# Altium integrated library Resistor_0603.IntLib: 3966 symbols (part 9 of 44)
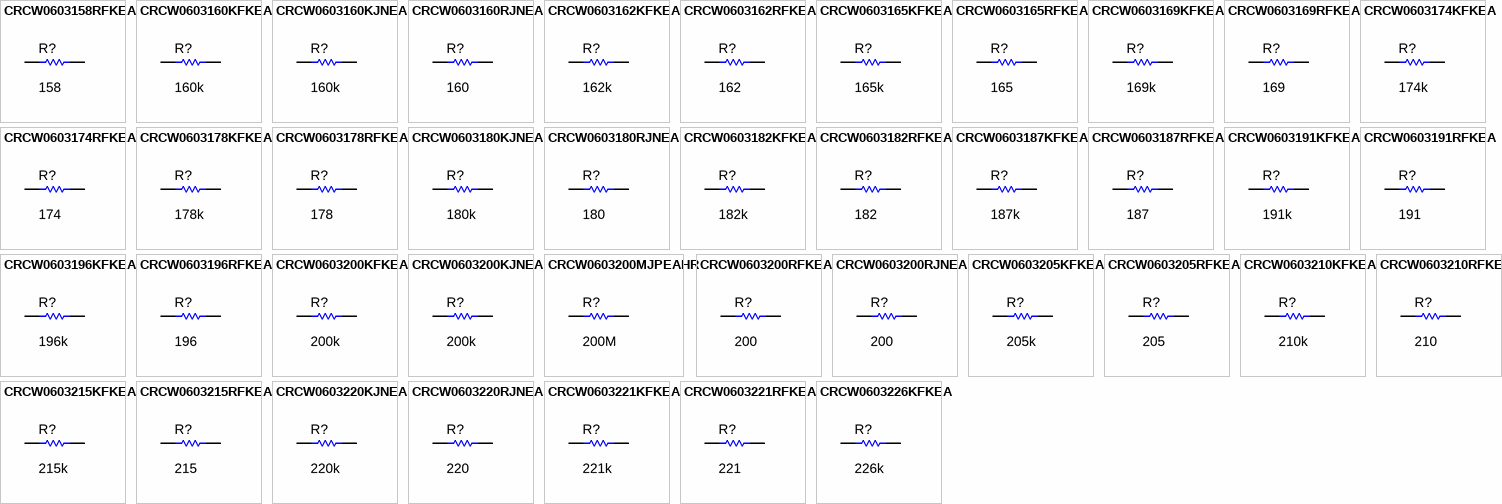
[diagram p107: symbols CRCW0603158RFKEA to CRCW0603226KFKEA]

## CRCW0603221RFKEA
designator R?  ValueDisplayed: 221  (hidden comment: CRCW0603221RFKEA)
RES, 221, 1%, 0.1 W, 0603; Manufacturer: Vishay-Dale; CompType: Resistor; Value: 221; Value_Code: 221R; Tolerance_%: 1; Power_W: 0.1; Value2: 0.1W; VDC_V: 75; TempCo: 100 ppm/C; SizeArea_mm2: 1.28; SizeX_mm: 1.6; SizeY_mm: 0.8; EIA_Code: E96; U/M: EA; AEC Category: Q200; Green_Lifecycle: Active; Green_REACh: Passed
signal-integrity model Resistor
simulation model Resistor
footprint 0603
footprint 0603M
footprint 0603L
footprint 0603_HV
footprint 0603S
pins: 1, 2

## CRCW0603226KFKEA
designator R?  ValueDisplayed: 226k  (hidden comment: CRCW0603226KFKEA)
RES, 226 k, 1%, 0.1 W, 0603; Manufacturer: Vishay-Dale; CompType: Resistor; Value: 226k; Res_ohm: 226000; Tolerance_%: 1; Power_W: 0.1; Value2: 0.1W; VDC_V: 75; TempCo: 100 ppm/C; SizeArea_mm2: 1.28; SizeX_mm: 1.6; SizeY_mm: 0.8; EIA_Code: E96; U/M: EA; AEC Category: Q200; Green_Lifecycle: Active; Green_REACh: Passed
signal-integrity model Resistor
simulation model Resistor
footprint 0603
footprint 0603M
footprint 0603L
footprint 0603_HV
footprint 0603S
pins: 1, 2

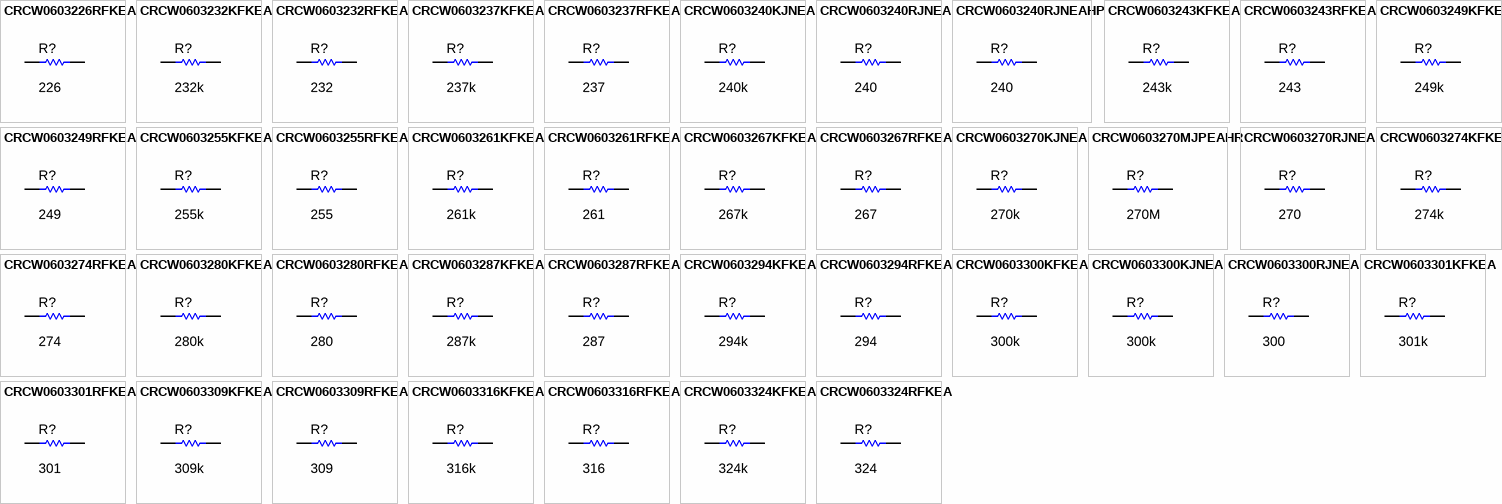
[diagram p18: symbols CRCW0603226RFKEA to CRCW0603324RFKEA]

## CRCW0603226RFKEA
designator R?  ValueDisplayed: 226  (hidden comment: CRCW0603226RFKEA)
RES, 226, 1%, 0.1 W, 0603; Manufacturer: Vishay-Dale; CompType: Resistor; Value: 226; Value_Code: 226R; Tolerance_%: 1; Power_W: 0.1; Value2: 0.1W; VDC_V: 75; TempCo: 100 ppm/C; SizeArea_mm2: 1.28; SizeX_mm: 1.6; SizeY_mm: 0.8; EIA_Code: E96; U/M: EA; AEC Category: Q200
signal-integrity model Resistor
simulation model Resistor
footprint 0603
footprint 0603M
footprint 0603L
footprint 0603_HV
footprint 0603S
pins: 1, 2

## CRCW0603232KFKEA
designator R?  ValueDisplayed: 232k  (hidden comment: CRCW0603232KFKEA)
RES, 232 k, 1%, 0.1 W, 0603; Manufacturer: Vishay-Dale; CompType: Resistor; Value: 232k; Res_ohm: 232000; Tolerance_%: 1; Power_W: 0.1; Value2: 0.1W; VDC_V: 75; TempCo: 100 ppm/C; SizeArea_mm2: 1.28; SizeX_mm: 1.6; SizeY_mm: 0.8; EIA_Code: E96; U/M: EA; AEC Category: Q200; Green_Lifecycle: Active; Green_REACh: Passed
signal-integrity model Resistor
simulation model Resistor
footprint 0603
footprint 0603M
footprint 0603L
footprint 0603_HV
footprint 0603S
pins: 1, 2

## CRCW0603232RFKEA
designator R?  ValueDisplayed: 232  (hidden comment: CRCW0603232RFKEA)
RES, 232, 1%, 0.1 W, 0603; Manufacturer: Vishay-Dale; CompType: Resistor; Value: 232; Value_Code: 232R; Tolerance_%: 1; Power_W: 0.1; Value2: 0.1W; VDC_V: 75; TempCo: 100 ppm/C; SizeArea_mm2: 1.28; SizeX_mm: 1.6; SizeY_mm: 0.8; EIA_Code: E96; U/M: EA; AEC Category: Q200
signal-integrity model Resistor
simulation model Resistor
footprint 0603
footprint 0603M
footprint 0603L
footprint 0603_HV
footprint 0603S
pins: 1, 2

## CRCW0603237KFKEA
designator R?  ValueDisplayed: 237k  (hidden comment: CRCW0603237KFKEA)
RES, 237 k, 1%, 0.1 W, 0603; Manufacturer: Vishay-Dale; CompType: Resistor; Value: 237k; Res_ohm: 237000; Tolerance_%: 1; Power_W: 0.1; Value2: 0.1W; VDC_V: 75; TempCo: 100 ppm/C; SizeArea_mm2: 1.28; SizeX_mm: 1.6; SizeY_mm: 0.8; EIA_Code: E96; U/M: EA; AEC Category: Q200; Green_Lifecycle: Active; Green_REACh: Passed
signal-integrity model Resistor
simulation model Resistor
footprint 0603
footprint 0603M
footprint 0603L
footprint 0603_HV
footprint 0603S
pins: 1, 2

## CRCW0603237RFKEA
designator R?  ValueDisplayed: 237  (hidden comment: CRCW0603237RFKEA)
RES, 237, 1%, 0.1 W, 0603; Manufacturer: Vishay-Dale; CompType: Resistor; Value: 237; Value_Code: 237R; Tolerance_%: 1; Power_W: 0.1; Value2: 0.1W; VDC_V: 75; TempCo: 100 ppm/C; SizeArea_mm2: 1.28; SizeX_mm: 1.6; SizeY_mm: 0.8; EIA_Code: E96; U/M: EA; AEC Category: Q200; Green_Lifecycle: Active; Green_REACh: Passed
signal-integrity model Resistor
simulation model Resistor
footprint 0603
footprint 0603M
footprint 0603L
footprint 0603_HV
footprint 0603S
pins: 1, 2

## CRCW0603240KJNEA
designator R?  ValueDisplayed: 240k  (hidden comment: CRCW0603240KJNEA)
RES, 240 k, 5%, 0.1 W, 0603; Manufacturer: Vishay-Dale; CompType: Resistor; Value: 240k; Res_ohm: 240000; Tolerance_%: 5; Power_W: 0.1; Value2: 0.1W; VDC_V: 75; TempCo: 200 ppm/C; SizeArea_mm2: 1.28; SizeX_mm: 1.6; SizeY_mm: 0.8; SizeZ_mm: 1; EIA_Code: E24; U/M: EA; AEC Category: Q200; Green_Lifecycle: Active; Green_REACh: Passed
signal-integrity model Resistor
simulation model Resistor
footprint 0603
footprint 0603M
footprint 0603L
footprint 0603_HV
footprint 0603S
pins: 1, 2

## CRCW0603240RJNEA
designator R?  ValueDisplayed: 240  (hidden comment: CRCW0603240RJNEA)
RES, 240, 5%, 0.1 W, 0603; Manufacturer: Vishay-Dale; CompType: Resistor; Value: 240; Value_Code: 240R; Tolerance_%: 5; Power_W: 0.1; Value2: 0.1W; VDC_V: 75; TempCo: 200 ppm/C; SizeArea_mm2: 1.28; SizeX_mm: 1.6; SizeY_mm: 0.8; SizeZ_mm: 1; EIA_Code: E24; U/M: EA; AEC Category: Q200; Green_Lifecycle: Active; Green_REACh: Passed
signal-integrity model Resistor
simulation model Resistor
footprint 0603
footprint 0603M
footprint 0603L
footprint 0603_HV
footprint 0603S
pins: 1, 2

## CRCW0603240RJNEAHP
designator R?  ValueDisplayed: 240  (hidden comment: CRCW0603240RJNEAHP)
RES, 240, 5%, 0.25 W, 0603; Manufacturer: Vishay-Dale; CompType: Resistor; Value: 240; Value_Code: 240R; Tolerance_%: 5; Power_W: 0.25; Value2: 0.25W; VDC_V: 75; TempCo: 200 ppm/C; SizeArea_mm2: 1.28; SizeX_mm: 1.6; SizeY_mm: 0.8; SizeZ_mm: 1; EIA_Code: E24; U/M: EA; AEC Category: Q200
signal-integrity model Resistor
simulation model Resistor
footprint 0603
footprint 0603M
footprint 0603L
footprint 0603_HV
footprint 0603S
pins: 1, 2

## CRCW0603243KFKEA
designator R?  ValueDisplayed: 243k  (hidden comment: CRCW0603243KFKEA)
RES, 243 k, 1%, 0.1 W, 0603; Manufacturer: Vishay-Dale; CompType: Resistor; Value: 243k; Res_ohm: 243000; Tolerance_%: 1; Power_W: 0.1; Value2: 0.1W; VDC_V: 75; TempCo: 100 ppm/C; SizeArea_mm2: 1.28; SizeX_mm: 1.6; SizeY_mm: 0.8; EIA_Code: E96; U/M: EA; AEC Category: Q200; Green_Lifecycle: Active; Green_REACh: Passed
signal-integrity model Resistor
simulation model Resistor
footprint 0603
footprint 0603M
footprint 0603L
footprint 0603_HV
footprint 0603S
pins: 1, 2

## CRCW0603243RFKEA
designator R?  ValueDisplayed: 243  (hidden comment: CRCW0603243RFKEA)
RES, 243, 1%, 0.1 W, 0603; Manufacturer: Vishay-Dale; CompType: Resistor; Value: 243; Value_Code: 243R; Tolerance_%: 1; Power_W: 0.1; Value2: 0.1W; VDC_V: 75; TempCo: 100 ppm/C; SizeArea_mm2: 1.28; SizeX_mm: 1.6; SizeY_mm: 0.8; EIA_Code: E96; U/M: EA; AEC Category: Q200
signal-integrity model Resistor
simulation model Resistor
footprint 0603
footprint 0603M
footprint 0603L
footprint 0603_HV
footprint 0603S
pins: 1, 2

## CRCW0603249KFKEA
designator R?  ValueDisplayed: 249k  (hidden comment: CRCW0603249KFKEA)
RES, 249 k, 1%, 0.1 W, 0603; Manufacturer: Vishay-Dale; CompType: Resistor; Value: 249k; Res_ohm: 249000; Tolerance_%: 1; Power_W: 0.1; Value2: 0.1W; VDC_V: 75; TempCo: 100 ppm/C; SizeArea_mm2: 1.28; SizeX_mm: 1.6; SizeY_mm: 0.8; EIA_Code: E96; U/M: EA; AEC Category: Q200; Green_Lifecycle: Active; Green_REACh: Passed
signal-integrity model Resistor
simulation model Resistor
footprint 0603
footprint 0603M
footprint 0603L
footprint 0603_HV
footprint 0603S
pins: 1, 2

## CRCW0603249RFKEA
designator R?  ValueDisplayed: 249  (hidden comment: CRCW0603249RFKEA)
RES, 249, 1%, 0.1 W, 0603; Manufacturer: Vishay-Dale; CompType: Resistor; Value: 249; Value_Code: 249R; Tolerance_%: 1; Power_W: 0.1; Value2: 0.1W; VDC_V: 75; TempCo: 100 ppm/C; SizeArea_mm2: 1.28; SizeX_mm: 1.6; SizeY_mm: 0.8; EIA_Code: E96; U/M: EA; AEC Category: Q200; Green_Lifecycle: Active; Green_REACh: Passed
signal-integrity model Resistor
simulation model Resistor
footprint 0603
footprint 0603M
footprint 0603L
footprint 0603_HV
footprint 0603S
pins: 1, 2

## CRCW0603255KFKEA
designator R?  ValueDisplayed: 255k  (hidden comment: CRCW0603255KFKEA)
RES, 255 k, 1%, 0.1 W, 0603; Manufacturer: Vishay-Dale; CompType: Resistor; Value: 255k; Res_ohm: 255000; Tolerance_%: 1; Power_W: 0.1; Value2: 0.1W; VDC_V: 75; TempCo: 100 ppm/C; SizeArea_mm2: 1.28; SizeX_mm: 1.6; SizeY_mm: 0.8; EIA_Code: E96; U/M: EA; AEC Category: Q200; Green_Lifecycle: Active; Green_REACh: Passed
signal-integrity model Resistor
simulation model Resistor
footprint 0603
footprint 0603M
footprint 0603L
footprint 0603_HV
footprint 0603S
pins: 1, 2

## CRCW0603255RFKEA
designator R?  ValueDisplayed: 255  (hidden comment: CRCW0603255RFKEA)
RES, 255, 1%, 0.1 W, 0603; Manufacturer: Vishay-Dale; CompType: Resistor; Value: 255; Value_Code: 255R; Tolerance_%: 1; Power_W: 0.1; Value2: 0.1W; VDC_V: 75; TempCo: 100 ppm/C; SizeArea_mm2: 1.28; SizeX_mm: 1.6; SizeY_mm: 0.8; EIA_Code: E96; U/M: EA; AEC Category: Q200
signal-integrity model Resistor
simulation model Resistor
footprint 0603
footprint 0603M
footprint 0603L
footprint 0603_HV
footprint 0603S
pins: 1, 2

## CRCW0603261KFKEA
designator R?  ValueDisplayed: 261k  (hidden comment: CRCW0603261KFKEA)
RES, 261 k, 1%, 0.1 W, 0603; Manufacturer: Vishay-Dale; CompType: Resistor; Value: 261k; Res_ohm: 261000; Tolerance_%: 1; Power_W: 0.1; Value2: 0.1W; VDC_V: 75; TempCo: 100 ppm/C; SizeArea_mm2: 1.28; SizeX_mm: 1.6; SizeY_mm: 0.8; EIA_Code: E96; U/M: EA; AEC Category: Q200; Green_Lifecycle: Active; Green_REACh: Passed
signal-integrity model Resistor
simulation model Resistor
footprint 0603
footprint 0603M
footprint 0603L
footprint 0603_HV
footprint 0603S
pins: 1, 2

## CRCW0603261RFKEA
designator R?  ValueDisplayed: 261  (hidden comment: CRCW0603261RFKEA)
RES, 261, 1%, 0.1 W, 0603; Manufacturer: Vishay-Dale; CompType: Resistor; Value: 261; Value_Code: 261R; Tolerance_%: 1; Power_W: 0.1; Value2: 0.1W; VDC_V: 75; TempCo: 100 ppm/C; SizeArea_mm2: 1.28; SizeX_mm: 1.6; SizeY_mm: 0.8; EIA_Code: E96; U/M: EA; AEC Category: Q200; Green_Lifecycle: Active; Green_REACh: Passed
signal-integrity model Resistor
simulation model Resistor
footprint 0603
footprint 0603M
footprint 0603L
footprint 0603_HV
footprint 0603S
pins: 1, 2

## CRCW0603267KFKEA
designator R?  ValueDisplayed: 267k  (hidden comment: CRCW0603267KFKEA)
RES, 267 k, 1%, 0.1 W, 0603; Manufacturer: Vishay-Dale; CompType: Resistor; Value: 267k; Res_ohm: 267000; Tolerance_%: 1; Power_W: 0.1; Value2: 0.1W; VDC_V: 75; TempCo: 100 ppm/C; SizeArea_mm2: 1.28; SizeX_mm: 1.6; SizeY_mm: 0.8; EIA_Code: E96; U/M: EA; AEC Category: Q200; Green_Lifecycle: Active; Green_REACh: Passed
signal-integrity model Resistor
simulation model Resistor
footprint 0603
footprint 0603M
footprint 0603L
footprint 0603_HV
footprint 0603S
pins: 1, 2

## CRCW0603267RFKEA
designator R?  ValueDisplayed: 267  (hidden comment: CRCW0603267RFKEA)
RES, 267, 1%, 0.1 W, 0603; Manufacturer: Vishay-Dale; CompType: Resistor; Value: 267; Value_Code: 267R; Tolerance_%: 1; Power_W: 0.1; Value2: 0.1W; VDC_V: 75; TempCo: 100 ppm/C; SizeArea_mm2: 1.28; SizeX_mm: 1.6; SizeY_mm: 0.8; EIA_Code: E96; U/M: EA; AEC Category: Q200; Green_Lifecycle: Active; Green_REACh: Passed
signal-integrity model Resistor
simulation model Resistor
footprint 0603
footprint 0603M
footprint 0603L
footprint 0603_HV
footprint 0603S
pins: 1, 2

## CRCW0603270KJNEA
designator R?  ValueDisplayed: 270k  (hidden comment: CRCW0603270KJNEA)
RES, 270 k, 5%, 0.1 W, 0603; Manufacturer: Vishay-Dale; CompType: Resistor; Value: 270k; Res_ohm: 270000; Tolerance_%: 5; Power_W: 0.1; Value2: 0.1W; VDC_V: 75; TempCo: 200 ppm/C; SizeArea_mm2: 1.28; SizeX_mm: 1.6; SizeY_mm: 0.8; SizeZ_mm: 1; EIA_Code: E24; U/M: EA; AEC Category: Q200
signal-integrity model Resistor
simulation model Resistor
footprint 0603
footprint 0603M
footprint 0603L
footprint 0603_HV
footprint 0603S
pins: 1, 2

## CRCW0603270MJPEAHR
designator R?  ValueDisplayed: 270M  (hidden comment: CRCW0603270MJPEAHR)
RES, 270 M, 5%, 0.1 W, 0603; Manufacturer: Vishay-Dale; CompType: Resistor; Value: 270Meg; Res_ohm: 270000000; Tolerance_%: 5; Power_W: 0.1; Value2: 0.1W; VDC_V: 75; TempCo: 500 ppm/C; SizeArea_mm2: 1.3175; SizeX_mm: 1.55; SizeY_mm: 0.85; SizeZ_mm: 0.5; U/M: EA; AEC Category: Q200; AEC Qualified: N
signal-integrity model Resistor
simulation model Resistor
footprint D11_0603
pins: 1, 2

## CRCW0603270RJNEA
designator R?  ValueDisplayed: 270  (hidden comment: CRCW0603270RJNEA)
RES, 270, 5%, 0.1 W, 0603; Manufacturer: Vishay-Dale; CompType: Resistor; Value: 270; Value_Code: 270R; Tolerance_%: 5; Power_W: 0.1; Value2: 0.1W; VDC_V: 75; TempCo: 200 ppm/C; SizeArea_mm2: 1.28; SizeX_mm: 1.6; SizeY_mm: 0.8; SizeZ_mm: 1; EIA_Code: E24; U/M: EA; AEC Category: Q200; Green_Lifecycle: Active; Green_REACh: Passed
signal-integrity model Resistor
simulation model Resistor
footprint 0603
footprint 0603M
footprint 0603L
footprint 0603_HV
footprint 0603S
pins: 1, 2

## CRCW0603274KFKEA
designator R?  ValueDisplayed: 274k  (hidden comment: CRCW0603274KFKEA)
RES, 274 k, 1%, 0.1 W, 0603; Manufacturer: Vishay-Dale; CompType: Resistor; Value: 274k; Res_ohm: 274000; Tolerance_%: 1; Power_W: 0.1; Value2: 0.1W; VDC_V: 75; TempCo: 100 ppm/C; SizeArea_mm2: 1.28; SizeX_mm: 1.6; SizeY_mm: 0.8; EIA_Code: E96; U/M: EA; AEC Category: Q200; Green_Lifecycle: Active; Green_REACh: Passed
signal-integrity model Resistor
simulation model Resistor
footprint 0603
footprint 0603M
footprint 0603L
footprint 0603_HV
footprint 0603S
pins: 1, 2

## CRCW0603274RFKEA
designator R?  ValueDisplayed: 274  (hidden comment: CRCW0603274RFKEA)
RES, 274, 1%, 0.1 W, 0603; Manufacturer: Vishay-Dale; CompType: Resistor; Value: 274; Value_Code: 274R; Tolerance_%: 1; Power_W: 0.1; Value2: 0.1W; VDC_V: 75; TempCo: 100 ppm/C; SizeArea_mm2: 1.28; SizeX_mm: 1.6; SizeY_mm: 0.8; EIA_Code: E96; U/M: EA; AEC Category: Q200
signal-integrity model Resistor
simulation model Resistor
footprint 0603
footprint 0603M
footprint 0603L
footprint 0603_HV
footprint 0603S
pins: 1, 2

## CRCW0603280KFKEA
designator R?  ValueDisplayed: 280k  (hidden comment: CRCW0603280KFKEA)
RES, 280 k, 1%, 0.1 W, 0603; Manufacturer: Vishay-Dale; CompType: Resistor; Value: 280k; Res_ohm: 280000; Tolerance_%: 1; Power_W: 0.1; Value2: 0.1W; VDC_V: 75; TempCo: 100 ppm/C; SizeArea_mm2: 1.28; SizeX_mm: 1.6; SizeY_mm: 0.8; EIA_Code: E96; U/M: EA; AEC Category: Q200; Green_Lifecycle: Active; Green_REACh: Passed
signal-integrity model Resistor
simulation model Resistor
footprint 0603
footprint 0603M
footprint 0603L
footprint 0603_HV
footprint 0603S
pins: 1, 2

## CRCW0603280RFKEA
designator R?  ValueDisplayed: 280  (hidden comment: CRCW0603280RFKEA)
RES, 280, 1%, 0.1 W, 0603; Manufacturer: Vishay-Dale; CompType: Resistor; Value: 280; Value_Code: 280R; Tolerance_%: 1; Power_W: 0.1; Value2: 0.1W; VDC_V: 75; TempCo: 100 ppm/C; SizeArea_mm2: 1.28; SizeX_mm: 1.6; SizeY_mm: 0.8; EIA_Code: E96; U/M: EA; AEC Category: Q200; Green_Lifecycle: Active; Green_REACh: Passed
signal-integrity model Resistor
simulation model Resistor
footprint 0603
footprint 0603M
footprint 0603L
footprint 0603_HV
footprint 0603S
pins: 1, 2

## CRCW0603287KFKEA
designator R?  ValueDisplayed: 287k  (hidden comment: CRCW0603287KFKEA)
RES, 287 k, 1%, 0.1 W, 0603; Manufacturer: Vishay-Dale; CompType: Resistor; Value: 287k; Res_ohm: 287000; Tolerance_%: 1; Power_W: 0.1; Value2: 0.1W; VDC_V: 75; TempCo: 100 ppm/C; SizeArea_mm2: 1.28; SizeX_mm: 1.6; SizeY_mm: 0.8; EIA_Code: E96; U/M: EA; AEC Category: Q200
signal-integrity model Resistor
simulation model Resistor
footprint 0603
footprint 0603M
footprint 0603L
footprint 0603_HV
footprint 0603S
pins: 1, 2

## CRCW0603287RFKEA
designator R?  ValueDisplayed: 287  (hidden comment: CRCW0603287RFKEA)
RES, 287, 1%, 0.1 W, 0603; Manufacturer: Vishay-Dale; CompType: Resistor; Value: 287; Value_Code: 287R; Tolerance_%: 1; Power_W: 0.1; Value2: 0.1W; VDC_V: 75; TempCo: 100 ppm/C; SizeArea_mm2: 1.28; SizeX_mm: 1.6; SizeY_mm: 0.8; EIA_Code: E96; U/M: EA; AEC Category: Q200
signal-integrity model Resistor
simulation model Resistor
footprint 0603
footprint 0603M
footprint 0603L
footprint 0603_HV
footprint 0603S
pins: 1, 2

## CRCW0603294KFKEA
designator R?  ValueDisplayed: 294k  (hidden comment: CRCW0603294KFKEA)
RES, 294 k, 1%, 0.1 W, 0603; Manufacturer: Vishay-Dale; CompType: Resistor; Value: 294k; Res_ohm: 294000; Tolerance_%: 1; Power_W: 0.1; Value2: 0.1W; VDC_V: 75; TempCo: 100 ppm/C; SizeArea_mm2: 1.28; SizeX_mm: 1.6; SizeY_mm: 0.8; EIA_Code: E96; U/M: EA; AEC Category: Q200
signal-integrity model Resistor
simulation model Resistor
footprint 0603
footprint 0603M
footprint 0603L
footprint 0603_HV
footprint 0603S
pins: 1, 2

## CRCW0603294RFKEA
designator R?  ValueDisplayed: 294  (hidden comment: CRCW0603294RFKEA)
RES, 294, 1%, 0.1 W, 0603; Manufacturer: Vishay-Dale; CompType: Resistor; Value: 294; Value_Code: 294R; Tolerance_%: 1; Power_W: 0.1; Value2: 0.1W; VDC_V: 75; TempCo: 100 ppm/C; SizeArea_mm2: 1.28; SizeX_mm: 1.6; SizeY_mm: 0.8; EIA_Code: E96; U/M: EA; AEC Category: Q200
signal-integrity model Resistor
simulation model Resistor
footprint 0603
footprint 0603M
footprint 0603L
footprint 0603_HV
footprint 0603S
pins: 1, 2

## CRCW0603300KFKEA
designator R?  ValueDisplayed: 300k  (hidden comment: CRCW0603300KFKEA)
RES, 300 k, 1%, 0.1 W, 0603; Manufacturer: Vishay-Dale; CompType: Resistor; Value: 300k; Res_ohm: 300000; Tolerance_%: 1; Power_W: 0.1; Value2: 0.1W; TempCo: 100 ppm/C; SizeArea_mm2: 1.28; SizeX_mm: 1.6; SizeY_mm: 0.8; U/M: EA; AEC Category: Q200
signal-integrity model Resistor
simulation model Resistor
footprint 0603
footprint 0603M
footprint 0603L
footprint 0603_HV
footprint 0603S
pins: 1, 2

## CRCW0603300KJNEA
designator R?  ValueDisplayed: 300k  (hidden comment: CRCW0603300KJNEA)
RES, 300 k, 5%, 0.1 W, 0603; Manufacturer: Vishay-Dale; CompType: Resistor; Value: 300k; Res_ohm: 300000; Tolerance_%: 5; Power_W: 0.1; Value2: 0.1W; VDC_V: 75; TempCo: 200 ppm/C; SizeArea_mm2: 1.28; SizeX_mm: 1.6; SizeY_mm: 0.8; SizeZ_mm: 1; EIA_Code: E24; U/M: EA; AEC Category: Q200; Green_Lifecycle: Active; Green_REACh: Passed
signal-integrity model Resistor
simulation model Resistor
footprint 0603
footprint 0603M
footprint 0603L
footprint 0603_HV
footprint 0603S
pins: 1, 2

## CRCW0603300RJNEA
designator R?  ValueDisplayed: 300  (hidden comment: CRCW0603300RJNEA)
RES, 300, 5%, 0.1 W, 0603; Manufacturer: Vishay-Dale; CompType: Resistor; Value: 300; Value_Code: 300R; Tolerance_%: 5; Power_W: 0.1; Value2: 0.1W; VDC_V: 75; TempCo: 200 ppm/C; SizeArea_mm2: 1.28; SizeX_mm: 1.6; SizeY_mm: 0.8; SizeZ_mm: 1; EIA_Code: E24; U/M: EA; AEC Category: Q200; Green_Lifecycle: Active; Green_REACh: Passed
signal-integrity model Resistor
simulation model Resistor
footprint 0603
footprint 0603M
footprint 0603L
footprint 0603_HV
footprint 0603S
pins: 1, 2

## CRCW0603301KFKEA
designator R?  ValueDisplayed: 301k  (hidden comment: CRCW0603301KFKEA)
RES, 301 k, 1%, 0.1 W, 0603; Manufacturer: Vishay-Dale; CompType: Resistor; Value: 301k; Res_ohm: 301000; Tolerance_%: 1; Power_W: 0.1; Value2: 0.1W; VDC_V: 75; TempCo: 100 ppm/C; SizeArea_mm2: 1.28; SizeX_mm: 1.6; SizeY_mm: 0.8; EIA_Code: E96; U/M: EA; AEC Category: Q200; Green_Lifecycle: Active; Green_REACh: Passed
signal-integrity model Resistor
simulation model Resistor
footprint 0603
footprint 0603M
footprint 0603L
footprint 0603_HV
footprint 0603S
pins: 1, 2

## CRCW0603301RFKEA
designator R?  ValueDisplayed: 301  (hidden comment: CRCW0603301RFKEA)
RES, 301, 1%, 0.1 W, 0603; Manufacturer: Vishay-Dale; CompType: Resistor; Value: 301; Value_Code: 301R; Tolerance_%: 1; Power_W: 0.1; Value2: 0.1W; VDC_V: 75; TempCo: 100 ppm/C; SizeArea_mm2: 1.28; SizeX_mm: 1.6; SizeY_mm: 0.8; EIA_Code: E96; U/M: EA; AEC Category: Q200; Green_Lifecycle: Active; Green_REACh: Passed
signal-integrity model Resistor
simulation model Resistor
footprint 0603
footprint 0603M
footprint 0603L
footprint 0603_HV
footprint 0603S
pins: 1, 2

## CRCW0603309KFKEA
designator R?  ValueDisplayed: 309k  (hidden comment: CRCW0603309KFKEA)
RES, 309 k, 1%, 0.1 W, 0603; Manufacturer: Vishay-Dale; CompType: Resistor; Value: 309k; Res_ohm: 309000; Tolerance_%: 1; Power_W: 0.1; Value2: 0.1W; VDC_V: 75; TempCo: 100 ppm/C; SizeArea_mm2: 1.28; SizeX_mm: 1.6; SizeY_mm: 0.8; EIA_Code: E96; U/M: EA; AEC Category: Q200; Green_Lifecycle: Active; Green_REACh: Passed
signal-integrity model Resistor
simulation model Resistor
footprint 0603
footprint 0603M
footprint 0603L
footprint 0603_HV
footprint 0603S
pins: 1, 2

## CRCW0603309RFKEA
designator R?  ValueDisplayed: 309  (hidden comment: CRCW0603309RFKEA)
RES, 309, 1%, 0.1 W, 0603; Manufacturer: Vishay-Dale; CompType: Resistor; Value: 309; Value_Code: 309R; Tolerance_%: 1; Power_W: 0.1; Value2: 0.1W; VDC_V: 75; TempCo: 100 ppm/C; SizeArea_mm2: 1.28; SizeX_mm: 1.6; SizeY_mm: 0.8; EIA_Code: E96; U/M: EA; AEC Category: Q200
signal-integrity model Resistor
simulation model Resistor
footprint 0603
footprint 0603M
footprint 0603L
footprint 0603_HV
footprint 0603S
pins: 1, 2

## CRCW0603316KFKEA
designator R?  ValueDisplayed: 316k  (hidden comment: CRCW0603316KFKEA)
RES, 316 k, 1%, 0.1 W, 0603; Manufacturer: Vishay-Dale; CompType: Resistor; Value: 316k; Res_ohm: 316000; Tolerance_%: 1; Power_W: 0.1; Value2: 0.1W; VDC_V: 75; TempCo: 100 ppm/C; SizeArea_mm2: 1.28; SizeX_mm: 1.6; SizeY_mm: 0.8; EIA_Code: E96; U/M: EA; AEC Category: Q200; Green_Lifecycle: Active; Green_REACh: Passed
signal-integrity model Resistor
simulation model Resistor
footprint 0603
footprint 0603M
footprint 0603L
footprint 0603_HV
footprint 0603S
pins: 1, 2

## CRCW0603316RFKEA
designator R?  ValueDisplayed: 316  (hidden comment: CRCW0603316RFKEA)
RES, 316, 1%, 0.1 W, 0603; Manufacturer: Vishay-Dale; CompType: Resistor; Value: 316; Value_Code: 316R; Tolerance_%: 1; Power_W: 0.1; Value2: 0.1W; VDC_V: 75; TempCo: 100 ppm/C; SizeArea_mm2: 1.28; SizeX_mm: 1.6; SizeY_mm: 0.8; EIA_Code: E96; U/M: EA; AEC Category: Q200; Green_Lifecycle: Active; Green_REACh: Passed
signal-integrity model Resistor
simulation model Resistor
footprint 0603
footprint 0603M
footprint 0603L
footprint 0603_HV
footprint 0603S
pins: 1, 2

## CRCW0603324KFKEA
designator R?  ValueDisplayed: 324k  (hidden comment: CRCW0603324KFKEA)
RES, 324 k, 1%, 0.1 W, 0603; Manufacturer: Vishay-Dale; CompType: Resistor; Value: 324k; Res_ohm: 324000; Tolerance_%: 1; Power_W: 0.1; Value2: 0.1W; VDC_V: 75; TempCo: 100 ppm/C; SizeArea_mm2: 1.28; SizeX_mm: 1.6; SizeY_mm: 0.8; EIA_Code: E96; U/M: EA; AEC Category: Q200; Green_Lifecycle: Active; Green_REACh: Passed
signal-integrity model Resistor
simulation model Resistor
footprint 0603
footprint 0603M
footprint 0603L
footprint 0603_HV
footprint 0603S
pins: 1, 2

## CRCW0603324RFKEA
designator R?  ValueDisplayed: 324  (hidden comment: CRCW0603324RFKEA)
RES, 324, 1%, 0.1 W, 0603; Manufacturer: Vishay-Dale; CompType: Resistor; Value: 324; Value_Code: 324R; Tolerance_%: 1; Power_W: 0.1; Value2: 0.1W; VDC_V: 75; TempCo: 100 ppm/C; SizeArea_mm2: 1.28; SizeX_mm: 1.6; SizeY_mm: 0.8; EIA_Code: E96; U/M: EA; AEC Category: Q200
signal-integrity model Resistor
simulation model Resistor
footprint 0603
footprint 0603M
footprint 0603L
footprint 0603_HV
footprint 0603S
pins: 1, 2

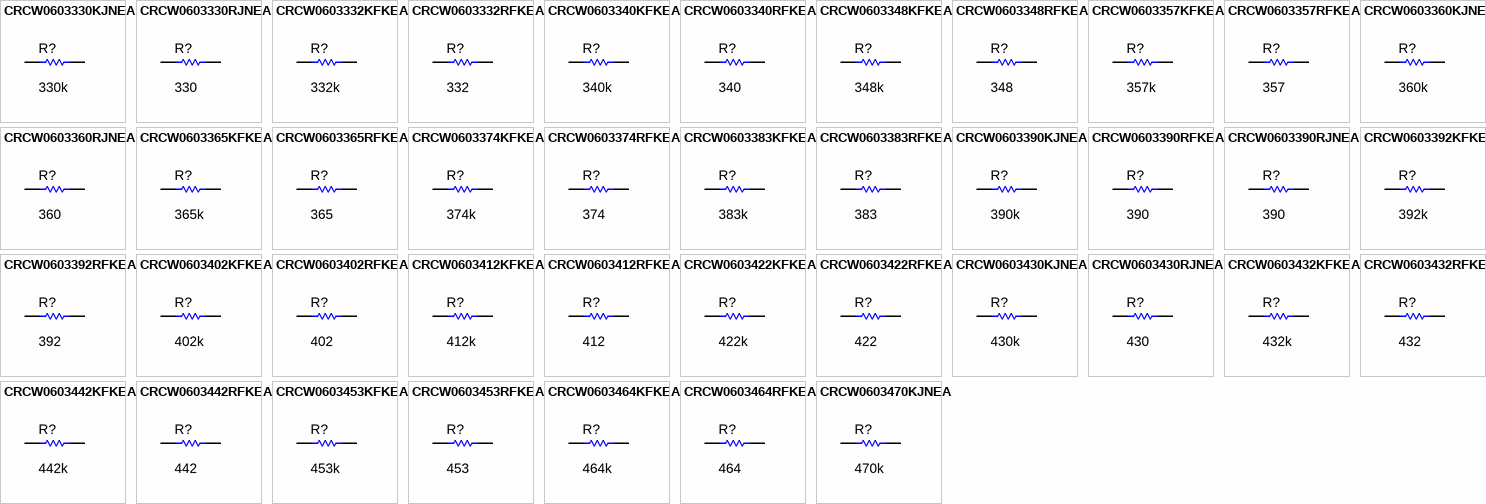
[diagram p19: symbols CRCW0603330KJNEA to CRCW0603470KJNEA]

## CRCW0603330KJNEA
designator R?  ValueDisplayed: 330k  (hidden comment: CRCW0603330KJNEA)
RES, 330 k, 5%, 0.1 W, 0603; Manufacturer: Vishay-Dale; CompType: Resistor; Value: 330k; Res_ohm: 330000; Tolerance_%: 5; Power_W: 0.1; Value2: 0.1W; VDC_V: 75; TempCo: 200 ppm/C; SizeArea_mm2: 1.28; SizeX_mm: 1.6; SizeY_mm: 0.8; SizeZ_mm: 1; EIA_Code: E24; U/M: EA; AEC Category: Q200; Green_Lifecycle: Active; Green_REACh: Passed
signal-integrity model Resistor
simulation model Resistor
footprint 0603
footprint 0603M
footprint 0603L
footprint 0603_HV
footprint 0603S
pins: 1, 2

## CRCW0603330RJNEA
designator R?  ValueDisplayed: 330  (hidden comment: CRCW0603330RJNEA)
RES, 330, 5%, 0.1 W, 0603; Manufacturer: Vishay-Dale; CompType: Resistor; Value: 330; Value_Code: 330R; Tolerance_%: 5; Power_W: 0.1; Value2: 0.1W; VDC_V: 75; TempCo: 200 ppm/C; SizeArea_mm2: 1.28; SizeX_mm: 1.6; SizeY_mm: 0.8; SizeZ_mm: 1; EIA_Code: E24; U/M: EA; AEC Category: Q200; Green_Lifecycle: Active; Green_REACh: Passed
signal-integrity model Resistor
simulation model Resistor
footprint 0603
footprint 0603M
footprint 0603L
footprint 0603_HV
footprint 0603S
pins: 1, 2

## CRCW0603332KFKEA
designator R?  ValueDisplayed: 332k  (hidden comment: CRCW0603332KFKEA)
RES, 332 k, 1%, 0.1 W, 0603; Manufacturer: Vishay-Dale; CompType: Resistor; Value: 332k; Res_ohm: 332000; Tolerance_%: 1; Power_W: 0.1; Value2: 0.1W; VDC_V: 75; TempCo: 100 ppm/C; SizeArea_mm2: 1.28; SizeX_mm: 1.6; SizeY_mm: 0.8; EIA_Code: E96; U/M: EA; AEC Category: Q200; Green_Lifecycle: Active; Green_REACh: Passed
signal-integrity model Resistor
simulation model Resistor
footprint 0603
footprint 0603M
footprint 0603L
footprint 0603_HV
footprint 0603S
pins: 1, 2

## CRCW0603332RFKEA
designator R?  ValueDisplayed: 332  (hidden comment: CRCW0603332RFKEA)
RES, 332, 1%, 0.1 W, 0603; Manufacturer: Vishay-Dale; CompType: Resistor; Value: 332; Value_Code: 332R; Tolerance_%: 1; Power_W: 0.1; Value2: 0.1W; VDC_V: 75; TempCo: 100 ppm/C; SizeArea_mm2: 1.28; SizeX_mm: 1.6; SizeY_mm: 0.8; EIA_Code: E96; U/M: EA; AEC Category: Q200
signal-integrity model Resistor
simulation model Resistor
footprint 0603
footprint 0603M
footprint 0603L
footprint 0603_HV
footprint 0603S
pins: 1, 2

## CRCW0603340KFKEA
designator R?  ValueDisplayed: 340k  (hidden comment: CRCW0603340KFKEA)
RES, 340 k, 1%, 0.1 W, 0603; Manufacturer: Vishay-Dale; CompType: Resistor; Value: 340k; Res_ohm: 340000; Tolerance_%: 1; Power_W: 0.1; Value2: 0.1W; VDC_V: 75; TempCo: 100 ppm/C; SizeArea_mm2: 1.28; SizeX_mm: 1.6; SizeY_mm: 0.8; EIA_Code: E96; U/M: EA; AEC Category: Q200; Green_Lifecycle: Active; Green_REACh: Passed
signal-integrity model Resistor
simulation model Resistor
footprint 0603
footprint 0603M
footprint 0603L
footprint 0603_HV
footprint 0603S
pins: 1, 2

## CRCW0603340RFKEA
designator R?  ValueDisplayed: 340  (hidden comment: CRCW0603340RFKEA)
RES, 340, 1%, 0.1 W, 0603; Manufacturer: Vishay-Dale; CompType: Resistor; Value: 340; Value_Code: 340R; Tolerance_%: 1; Power_W: 0.1; Value2: 0.1W; VDC_V: 75; TempCo: 100 ppm/C; SizeArea_mm2: 1.28; SizeX_mm: 1.6; SizeY_mm: 0.8; EIA_Code: E96; U/M: EA; AEC Category: Q200; Green_Lifecycle: Active; Green_REACh: Passed
signal-integrity model Resistor
simulation model Resistor
footprint 0603
footprint 0603M
footprint 0603L
footprint 0603_HV
footprint 0603S
pins: 1, 2

## CRCW0603348KFKEA
designator R?  ValueDisplayed: 348k  (hidden comment: CRCW0603348KFKEA)
RES, 348 k, 1%, 0.1 W, 0603; Manufacturer: Vishay-Dale; CompType: Resistor; Value: 348k; Res_ohm: 348000; Tolerance_%: 1; Power_W: 0.1; Value2: 0.1W; VDC_V: 75; TempCo: 100 ppm/C; SizeArea_mm2: 1.28; SizeX_mm: 1.6; SizeY_mm: 0.8; EIA_Code: E96; U/M: EA; AEC Category: Q200; Green_Lifecycle: Active; Green_REACh: Passed
signal-integrity model Resistor
simulation model Resistor
footprint 0603
footprint 0603M
footprint 0603L
footprint 0603_HV
footprint 0603S
pins: 1, 2

## CRCW0603348RFKEA
designator R?  ValueDisplayed: 348  (hidden comment: CRCW0603348RFKEA)
RES, 348, 1%, 0.1 W, 0603; Manufacturer: Vishay-Dale; CompType: Resistor; Value: 348; Value_Code: 348R; Tolerance_%: 1; Power_W: 0.1; Value2: 0.1W; VDC_V: 75; TempCo: 100 ppm/C; SizeArea_mm2: 1.28; SizeX_mm: 1.6; SizeY_mm: 0.8; EIA_Code: E96; U/M: EA; AEC Category: Q200; Green_Lifecycle: Active; Green_REACh: Passed
signal-integrity model Resistor
simulation model Resistor
footprint 0603
footprint 0603M
footprint 0603L
footprint 0603_HV
footprint 0603S
pins: 1, 2

## CRCW0603357KFKEA
designator R?  ValueDisplayed: 357k  (hidden comment: CRCW0603357KFKEA)
RES, 357 k, 1%, 0.1 W, 0603; Manufacturer: Vishay-Dale; CompType: Resistor; Value: 357k; Res_ohm: 357000; Tolerance_%: 1; Power_W: 0.1; Value2: 0.1W; VDC_V: 75; TempCo: 100 ppm/C; SizeArea_mm2: 1.28; SizeX_mm: 1.6; SizeY_mm: 0.8; EIA_Code: E96; U/M: EA; AEC Category: Q200
signal-integrity model Resistor
simulation model Resistor
footprint 0603
footprint 0603M
footprint 0603L
footprint 0603_HV
footprint 0603S
pins: 1, 2

## CRCW0603357RFKEA
designator R?  ValueDisplayed: 357  (hidden comment: CRCW0603357RFKEA)
RES, 357, 1%, 0.1 W, 0603; Manufacturer: Vishay-Dale; CompType: Resistor; Value: 357; Value_Code: 357R; Tolerance_%: 1; Power_W: 0.1; Value2: 0.1W; VDC_V: 75; TempCo: 100 ppm/C; SizeArea_mm2: 1.28; SizeX_mm: 1.6; SizeY_mm: 0.8; EIA_Code: E96; U/M: EA; AEC Category: Q200
signal-integrity model Resistor
simulation model Resistor
footprint 0603
footprint 0603M
footprint 0603L
footprint 0603_HV
footprint 0603S
pins: 1, 2

## CRCW0603360KJNEA
designator R?  ValueDisplayed: 360k  (hidden comment: CRCW0603360KJNEA)
RES, 360 k, 5%, 0.1 W, 0603; Manufacturer: Vishay-Dale; CompType: Resistor; Value: 360k; Res_ohm: 360000; Tolerance_%: 5; Power_W: 0.1; Value2: 0.1W; VDC_V: 75; TempCo: 200 ppm/C; SizeArea_mm2: 1.28; SizeX_mm: 1.6; SizeY_mm: 0.8; SizeZ_mm: 1; EIA_Code: E24; U/M: EA; AEC Category: Q200
signal-integrity model Resistor
simulation model Resistor
footprint 0603
footprint 0603M
footprint 0603L
footprint 0603_HV
footprint 0603S
pins: 1, 2

## CRCW0603360RJNEA
designator R?  ValueDisplayed: 360  (hidden comment: CRCW0603360RJNEA)
RES, 360, 5%, 0.1 W, 0603; Manufacturer: Vishay-Dale; CompType: Resistor; Value: 360; Value_Code: 360R; Tolerance_%: 5; Power_W: 0.1; Value2: 0.1W; VDC_V: 75; TempCo: 200 ppm/C; SizeArea_mm2: 1.28; SizeX_mm: 1.6; SizeY_mm: 0.8; SizeZ_mm: 1; EIA_Code: E24; U/M: EA; AEC Category: Q200; Green_Lifecycle: Active; Green_REACh: Passed
signal-integrity model Resistor
simulation model Resistor
footprint 0603
footprint 0603M
footprint 0603L
footprint 0603_HV
footprint 0603S
pins: 1, 2

## CRCW0603365KFKEA
designator R?  ValueDisplayed: 365k  (hidden comment: CRCW0603365KFKEA)
RES, 365 k, 1%, 0.1 W, 0603; Manufacturer: Vishay-Dale; CompType: Resistor; Value: 365k; Res_ohm: 365000; Tolerance_%: 1; Power_W: 0.1; Value2: 0.1W; VDC_V: 75; TempCo: 100 ppm/C; SizeArea_mm2: 1.28; SizeX_mm: 1.6; SizeY_mm: 0.8; EIA_Code: E96; U/M: EA; AEC Category: Q200; Green_Lifecycle: Active; Green_REACh: Passed
signal-integrity model Resistor
simulation model Resistor
footprint 0603
footprint 0603M
footprint 0603L
footprint 0603_HV
footprint 0603S
pins: 1, 2

## CRCW0603365RFKEA
designator R?  ValueDisplayed: 365  (hidden comment: CRCW0603365RFKEA)
RES, 365, 1%, 0.1 W, 0603; Manufacturer: Vishay-Dale; CompType: Resistor; Value: 365; Value_Code: 365R; Tolerance_%: 1; Power_W: 0.1; Value2: 0.1W; VDC_V: 75; TempCo: 100 ppm/C; SizeArea_mm2: 1.28; SizeX_mm: 1.6; SizeY_mm: 0.8; EIA_Code: E96; U/M: EA; AEC Category: Q200; Green_Lifecycle: Active; Green_REACh: Passed
signal-integrity model Resistor
simulation model Resistor
footprint 0603
footprint 0603M
footprint 0603L
footprint 0603_HV
footprint 0603S
pins: 1, 2

## CRCW0603374KFKEA
designator R?  ValueDisplayed: 374k  (hidden comment: CRCW0603374KFKEA)
RES, 374 k, 1%, 0.1 W, 0603; Manufacturer: Vishay-Dale; CompType: Resistor; Value: 374k; Res_ohm: 374000; Tolerance_%: 1; Power_W: 0.1; Value2: 0.1W; VDC_V: 75; TempCo: 100 ppm/C; SizeArea_mm2: 1.28; SizeX_mm: 1.6; SizeY_mm: 0.8; EIA_Code: E96; U/M: EA; AEC Category: Q200; Green_Lifecycle: Active; Green_REACh: Passed
signal-integrity model Resistor
simulation model Resistor
footprint 0603
footprint 0603M
footprint 0603L
footprint 0603_HV
footprint 0603S
pins: 1, 2

## CRCW0603374RFKEA
designator R?  ValueDisplayed: 374  (hidden comment: CRCW0603374RFKEA)
RES, 374, 1%, 0.1 W, 0603; Manufacturer: Vishay-Dale; CompType: Resistor; Value: 374; Value_Code: 374R; Tolerance_%: 1; Power_W: 0.1; Value2: 0.1W; VDC_V: 75; TempCo: 100 ppm/C; SizeArea_mm2: 1.28; SizeX_mm: 1.6; SizeY_mm: 0.8; EIA_Code: E96; U/M: EA; AEC Category: Q200; Green_Lifecycle: Active; Green_REACh: Passed
signal-integrity model Resistor
simulation model Resistor
footprint 0603
footprint 0603M
footprint 0603L
footprint 0603_HV
footprint 0603S
pins: 1, 2

## CRCW0603383KFKEA
designator R?  ValueDisplayed: 383k  (hidden comment: CRCW0603383KFKEA)
RES, 383 k, 1%, 0.1 W, 0603; Manufacturer: Vishay-Dale; CompType: Resistor; Value: 383k; Res_ohm: 383000; Tolerance_%: 1; Power_W: 0.1; Value2: 0.1W; VDC_V: 75; TempCo: 100 ppm/C; SizeArea_mm2: 1.28; SizeX_mm: 1.6; SizeY_mm: 0.8; EIA_Code: E96; U/M: EA; AEC Category: Q200
signal-integrity model Resistor
simulation model Resistor
footprint 0603
footprint 0603M
footprint 0603L
footprint 0603_HV
footprint 0603S
pins: 1, 2

## CRCW0603383RFKEA
designator R?  ValueDisplayed: 383  (hidden comment: CRCW0603383RFKEA)
RES, 383, 1%, 0.1 W, 0603; Manufacturer: Vishay-Dale; CompType: Resistor; Value: 383; Value_Code: 383R; Tolerance_%: 1; Power_W: 0.1; Value2: 0.1W; VDC_V: 75; TempCo: 100 ppm/C; SizeArea_mm2: 1.28; SizeX_mm: 1.6; SizeY_mm: 0.8; EIA_Code: E96; U/M: EA; AEC Category: Q200
signal-integrity model Resistor
simulation model Resistor
footprint 0603
footprint 0603M
footprint 0603L
footprint 0603_HV
footprint 0603S
pins: 1, 2

## CRCW0603390KJNEA
designator R?  ValueDisplayed: 390k  (hidden comment: CRCW0603390KJNEA)
RES, 390 k, 5%, 0.1 W, 0603; Manufacturer: Vishay-Dale; CompType: Resistor; Value: 390k; Res_ohm: 390000; Tolerance_%: 5; Power_W: 0.1; Value2: 0.1W; VDC_V: 75; TempCo: 200 ppm/C; SizeArea_mm2: 1.28; SizeX_mm: 1.6; SizeY_mm: 0.8; SizeZ_mm: 1; EIA_Code: E24; U/M: EA; AEC Category: Q200
signal-integrity model Resistor
simulation model Resistor
footprint 0603
footprint 0603M
footprint 0603L
footprint 0603_HV
footprint 0603S
pins: 1, 2

## CRCW0603390RFKEA
designator R?  ValueDisplayed: 390  (hidden comment: CRCW0603390RFKEA)
RES, 390, 1%, 0.1 W, 0603; Manufacturer: Vishay-Dale; CompType: Resistor; Value: 390; Value_Code: 390R; Tolerance_%: 1; Power_W: 0.1; Value2: 0.1W; VDC_V: 75; TempCo: 100 ppm/C; SizeArea_mm2: 1.28; SizeX_mm: 1.6; SizeY_mm: 0.8; U/M: EA; AEC Category: Q200
signal-integrity model Resistor
simulation model Resistor
footprint 0603
footprint 0603M
footprint 0603L
footprint 0603_HV
footprint 0603S
pins: 1, 2

## CRCW0603390RJNEA
designator R?  ValueDisplayed: 390  (hidden comment: CRCW0603390RJNEA)
RES, 390, 5%, 0.1 W, 0603; Manufacturer: Vishay-Dale; CompType: Resistor; Value: 390; Value_Code: 390R; Tolerance_%: 5; Power_W: 0.1; Value2: 0.1W; VDC_V: 75; TempCo: 200 ppm/C; SizeArea_mm2: 1.28; SizeX_mm: 1.6; SizeY_mm: 0.8; SizeZ_mm: 1; EIA_Code: E24; U/M: EA; AEC Category: Q200; Green_Lifecycle: Active; Green_REACh: Passed
signal-integrity model Resistor
simulation model Resistor
footprint 0603
footprint 0603M
footprint 0603L
footprint 0603_HV
footprint 0603S
pins: 1, 2

## CRCW0603392KFKEA
designator R?  ValueDisplayed: 392k  (hidden comment: CRCW0603392KFKEA)
RES, 392 k, 1%, 0.1 W, 0603; Manufacturer: Vishay-Dale; CompType: Resistor; Value: 392k; Res_ohm: 392000; Tolerance_%: 1; Power_W: 0.1; Value2: 0.1W; VDC_V: 75; TempCo: 100 ppm/C; SizeArea_mm2: 1.28; SizeX_mm: 1.6; SizeY_mm: 0.8; EIA_Code: E96; U/M: EA; AEC Category: Q200
signal-integrity model Resistor
simulation model Resistor
footprint 0603
footprint 0603M
footprint 0603L
footprint 0603_HV
footprint 0603S
pins: 1, 2

## CRCW0603392RFKEA
designator R?  ValueDisplayed: 392  (hidden comment: CRCW0603392RFKEA)
RES, 392, 1%, 0.1 W, 0603; Manufacturer: Vishay-Dale; CompType: Resistor; Value: 392; Value_Code: 392R; Tolerance_%: 1; Power_W: 0.1; Value2: 0.1W; VDC_V: 75; TempCo: 100 ppm/C; SizeArea_mm2: 1.28; SizeX_mm: 1.6; SizeY_mm: 0.8; EIA_Code: E96; U/M: EA; AEC Category: Q200; Green_Lifecycle: Active; Green_REACh: Passed
signal-integrity model Resistor
simulation model Resistor
footprint 0603
footprint 0603M
footprint 0603L
footprint 0603_HV
footprint 0603S
pins: 1, 2

## CRCW0603402KFKEA
designator R?  ValueDisplayed: 402k  (hidden comment: CRCW0603402KFKEA)
RES, 402 k, 1%, 0.1 W, 0603; Manufacturer: Vishay-Dale; CompType: Resistor; Value: 402k; Res_ohm: 402000; Tolerance_%: 1; Power_W: 0.1; Value2: 0.1W; VDC_V: 75; TempCo: 100 ppm/C; SizeArea_mm2: 1.28; SizeX_mm: 1.6; SizeY_mm: 0.8; EIA_Code: E96; U/M: EA; AEC Category: Q200; Green_Lifecycle: Active; Green_REACh: Passed
signal-integrity model Resistor
simulation model Resistor
footprint 0603
footprint 0603M
footprint 0603L
footprint 0603_HV
footprint 0603S
pins: 1, 2

## CRCW0603402RFKEA
designator R?  ValueDisplayed: 402  (hidden comment: CRCW0603402RFKEA)
RES, 402, 1%, 0.1 W, 0603; Manufacturer: Vishay-Dale; CompType: Resistor; Value: 402; Value_Code: 402R; Tolerance_%: 1; Power_W: 0.1; Value2: 0.1W; VDC_V: 75; TempCo: 100 ppm/C; SizeArea_mm2: 1.28; SizeX_mm: 1.6; SizeY_mm: 0.8; EIA_Code: E96; U/M: EA; AEC Category: Q200
signal-integrity model Resistor
simulation model Resistor
footprint 0603
footprint 0603M
footprint 0603L
footprint 0603_HV
footprint 0603S
pins: 1, 2

## CRCW0603412KFKEA
designator R?  ValueDisplayed: 412k  (hidden comment: CRCW0603412KFKEA)
RES, 412 k, 1%, 0.1 W, 0603; Manufacturer: Vishay-Dale; CompType: Resistor; Value: 412k; Res_ohm: 412000; Tolerance_%: 1; Power_W: 0.1; Value2: 0.1W; VDC_V: 75; TempCo: 100 ppm/C; SizeArea_mm2: 1.28; SizeX_mm: 1.6; SizeY_mm: 0.8; EIA_Code: E96; U/M: EA; AEC Category: Q200
signal-integrity model Resistor
simulation model Resistor
footprint 0603
footprint 0603M
footprint 0603L
footprint 0603_HV
footprint 0603S
pins: 1, 2

## CRCW0603412RFKEA
designator R?  ValueDisplayed: 412  (hidden comment: CRCW0603412RFKEA)
RES, 412, 1%, 0.1 W, 0603; Manufacturer: Vishay-Dale; CompType: Resistor; Value: 412; Value_Code: 412R; Tolerance_%: 1; Power_W: 0.1; Value2: 0.1W; VDC_V: 75; TempCo: 100 ppm/C; SizeArea_mm2: 1.28; SizeX_mm: 1.6; SizeY_mm: 0.8; EIA_Code: E96; U/M: EA; AEC Category: Q200
signal-integrity model Resistor
simulation model Resistor
footprint 0603
footprint 0603M
footprint 0603L
footprint 0603_HV
footprint 0603S
pins: 1, 2

## CRCW0603422KFKEA
designator R?  ValueDisplayed: 422k  (hidden comment: CRCW0603422KFKEA)
RES, 422 k, 1%, 0.1 W, 0603; Manufacturer: Vishay-Dale; CompType: Resistor; Value: 422k; Res_ohm: 422000; Tolerance_%: 1; Power_W: 0.1; Value2: 0.1W; VDC_V: 75; TempCo: 100 ppm/C; SizeArea_mm2: 1.28; SizeX_mm: 1.6; SizeY_mm: 0.8; EIA_Code: E96; U/M: EA; AEC Category: Q200
signal-integrity model Resistor
simulation model Resistor
footprint 0603
footprint 0603M
footprint 0603L
footprint 0603_HV
footprint 0603S
pins: 1, 2

## CRCW0603422RFKEA
designator R?  ValueDisplayed: 422  (hidden comment: CRCW0603422RFKEA)
RES, 422, 1%, 0.1 W, 0603; Manufacturer: Vishay-Dale; CompType: Resistor; Value: 422; Value_Code: 422R; Tolerance_%: 1; Power_W: 0.1; Value2: 0.1W; VDC_V: 75; TempCo: 100 ppm/C; SizeArea_mm2: 1.28; SizeX_mm: 1.6; SizeY_mm: 0.8; EIA_Code: E96; U/M: EA; AEC Category: Q200
signal-integrity model Resistor
simulation model Resistor
footprint 0603
footprint 0603M
footprint 0603L
footprint 0603_HV
footprint 0603S
pins: 1, 2

## CRCW0603430KJNEA
designator R?  ValueDisplayed: 430k  (hidden comment: CRCW0603430KJNEA)
RES, 430 k, 5%, 0.1 W, 0603; Manufacturer: Vishay-Dale; CompType: Resistor; Value: 430k; Res_ohm: 430000; Tolerance_%: 5; Power_W: 0.1; Value2: 0.1W; VDC_V: 75; TempCo: 200 ppm/C; SizeArea_mm2: 1.28; SizeX_mm: 1.6; SizeY_mm: 0.8; SizeZ_mm: 1; EIA_Code: E24; U/M: EA; AEC Category: Q200
signal-integrity model Resistor
simulation model Resistor
footprint 0603
footprint 0603M
footprint 0603L
footprint 0603_HV
footprint 0603S
pins: 1, 2

## CRCW0603430RJNEA
designator R?  ValueDisplayed: 430  (hidden comment: CRCW0603430RJNEA)
RES, 430, 5%, 0.1 W, 0603; Manufacturer: Vishay-Dale; CompType: Resistor; Value: 430; Value_Code: 430R; Tolerance_%: 5; Power_W: 0.1; Value2: 0.1W; VDC_V: 75; TempCo: 200 ppm/C; SizeArea_mm2: 1.28; SizeX_mm: 1.6; SizeY_mm: 0.8; SizeZ_mm: 1; EIA_Code: E24; U/M: EA; AEC Category: Q200
signal-integrity model Resistor
simulation model Resistor
footprint 0603
footprint 0603M
footprint 0603L
footprint 0603_HV
footprint 0603S
pins: 1, 2

## CRCW0603432KFKEA
designator R?  ValueDisplayed: 432k  (hidden comment: CRCW0603432KFKEA)
RES, 432 k, 1%, 0.1 W, 0603; Manufacturer: Vishay-Dale; CompType: Resistor; Value: 432k; Res_ohm: 432000; Tolerance_%: 1; Power_W: 0.1; Value2: 0.1W; VDC_V: 75; TempCo: 100 ppm/C; SizeArea_mm2: 1.28; SizeX_mm: 1.6; SizeY_mm: 0.8; EIA_Code: E96; U/M: EA; AEC Category: Q200; Green_Lifecycle: Active; Green_REACh: Passed
signal-integrity model Resistor
simulation model Resistor
footprint 0603
footprint 0603M
footprint 0603L
footprint 0603_HV
footprint 0603S
pins: 1, 2

## CRCW0603432RFKEA
designator R?  ValueDisplayed: 432  (hidden comment: CRCW0603432RFKEA)
RES, 432, 1%, 0.1 W, 0603; Manufacturer: Vishay-Dale; CompType: Resistor; Value: 432; Value_Code: 432R; Tolerance_%: 1; Power_W: 0.1; Value2: 0.1W; VDC_V: 75; TempCo: 100 ppm/C; SizeArea_mm2: 1.28; SizeX_mm: 1.6; SizeY_mm: 0.8; EIA_Code: E96; U/M: EA; AEC Category: Q200
signal-integrity model Resistor
simulation model Resistor
footprint 0603
footprint 0603M
footprint 0603L
footprint 0603_HV
footprint 0603S
pins: 1, 2

## CRCW0603442KFKEA
designator R?  ValueDisplayed: 442k  (hidden comment: CRCW0603442KFKEA)
RES, 442 k, 1%, 0.1 W, 0603; Manufacturer: Vishay-Dale; CompType: Resistor; Value: 442k; Res_ohm: 442000; Tolerance_%: 1; Power_W: 0.1; Value2: 0.1W; VDC_V: 75; TempCo: 100 ppm/C; SizeArea_mm2: 1.28; SizeX_mm: 1.6; SizeY_mm: 0.8; EIA_Code: E96; U/M: EA; AEC Category: Q200; Green_Lifecycle: Active; Green_REACh: Passed
signal-integrity model Resistor
simulation model Resistor
footprint 0603
footprint 0603M
footprint 0603L
footprint 0603_HV
footprint 0603S
pins: 1, 2

## CRCW0603442RFKEA
designator R?  ValueDisplayed: 442  (hidden comment: CRCW0603442RFKEA)
RES, 442, 1%, 0.1 W, 0603; Manufacturer: Vishay-Dale; CompType: Resistor; Value: 442; Value_Code: 442R; Tolerance_%: 1; Power_W: 0.1; Value2: 0.1W; VDC_V: 75; TempCo: 100 ppm/C; SizeArea_mm2: 1.28; SizeX_mm: 1.6; SizeY_mm: 0.8; EIA_Code: E96; U/M: EA; AEC Category: Q200
signal-integrity model Resistor
simulation model Resistor
footprint 0603
footprint 0603M
footprint 0603L
footprint 0603_HV
footprint 0603S
pins: 1, 2

## CRCW0603453KFKEA
designator R?  ValueDisplayed: 453k  (hidden comment: CRCW0603453KFKEA)
RES, 453 k, 1%, 0.1 W, 0603; Manufacturer: Vishay-Dale; CompType: Resistor; Value: 453k; Res_ohm: 453000; Tolerance_%: 1; Power_W: 0.1; Value2: 0.1W; VDC_V: 75; TempCo: 100 ppm/C; SizeArea_mm2: 1.28; SizeX_mm: 1.6; SizeY_mm: 0.8; EIA_Code: E96; U/M: EA; AEC Category: Q200
signal-integrity model Resistor
simulation model Resistor
footprint 0603
footprint 0603M
footprint 0603L
footprint 0603_HV
footprint 0603S
pins: 1, 2

## CRCW0603453RFKEA
designator R?  ValueDisplayed: 453  (hidden comment: CRCW0603453RFKEA)
RES, 453, 1%, 0.1 W, 0603; Manufacturer: Vishay-Dale; CompType: Resistor; Value: 453; Value_Code: 453R; Tolerance_%: 1; Power_W: 0.1; Value2: 0.1W; VDC_V: 75; TempCo: 100 ppm/C; SizeArea_mm2: 1.28; SizeX_mm: 1.6; SizeY_mm: 0.8; EIA_Code: E96; U/M: EA; AEC Category: Q200
signal-integrity model Resistor
simulation model Resistor
footprint 0603
footprint 0603M
footprint 0603L
footprint 0603_HV
footprint 0603S
pins: 1, 2

## CRCW0603464KFKEA
designator R?  ValueDisplayed: 464k  (hidden comment: CRCW0603464KFKEA)
RES, 464 k, 1%, 0.1 W, 0603; Manufacturer: Vishay-Dale; CompType: Resistor; Value: 464k; Res_ohm: 464000; Tolerance_%: 1; Power_W: 0.1; Value2: 0.1W; VDC_V: 75; TempCo: 100 ppm/C; SizeArea_mm2: 1.28; SizeX_mm: 1.6; SizeY_mm: 0.8; EIA_Code: E96; U/M: EA; AEC Category: Q200
signal-integrity model Resistor
simulation model Resistor
footprint 0603
footprint 0603M
footprint 0603L
footprint 0603_HV
footprint 0603S
pins: 1, 2

## CRCW0603464RFKEA
designator R?  ValueDisplayed: 464  (hidden comment: CRCW0603464RFKEA)
RES, 464, 1%, 0.1 W, 0603; Manufacturer: Vishay-Dale; CompType: Resistor; Value: 464; Value_Code: 464R; Tolerance_%: 1; Power_W: 0.1; Value2: 0.1W; VDC_V: 75; TempCo: 100 ppm/C; SizeArea_mm2: 1.28; SizeX_mm: 1.6; SizeY_mm: 0.8; EIA_Code: E96; U/M: EA; AEC Category: Q200
signal-integrity model Resistor
simulation model Resistor
footprint 0603
footprint 0603M
footprint 0603L
footprint 0603_HV
footprint 0603S
pins: 1, 2

## CRCW0603470KJNEA
designator R?  ValueDisplayed: 470k  (hidden comment: CRCW0603470KJNEA)
RES, 470 k, 5%, 0.1 W, 0603; Manufacturer: Vishay-Dale; CompType: Resistor; Value: 470k; Res_ohm: 470000; Tolerance_%: 5; Power_W: 0.1; Value2: 0.1W; VDC_V: 75; TempCo: 200 ppm/C; SizeArea_mm2: 1.28; SizeX_mm: 1.6; SizeY_mm: 0.8; SizeZ_mm: 1; EIA_Code: E24; U/M: EA; AEC Category: Q200; Green_Lifecycle: Active; Green_REACh: Passed
signal-integrity model Resistor
simulation model Resistor
footprint 0603
footprint 0603M
footprint 0603L
footprint 0603_HV
footprint 0603S
pins: 1, 2

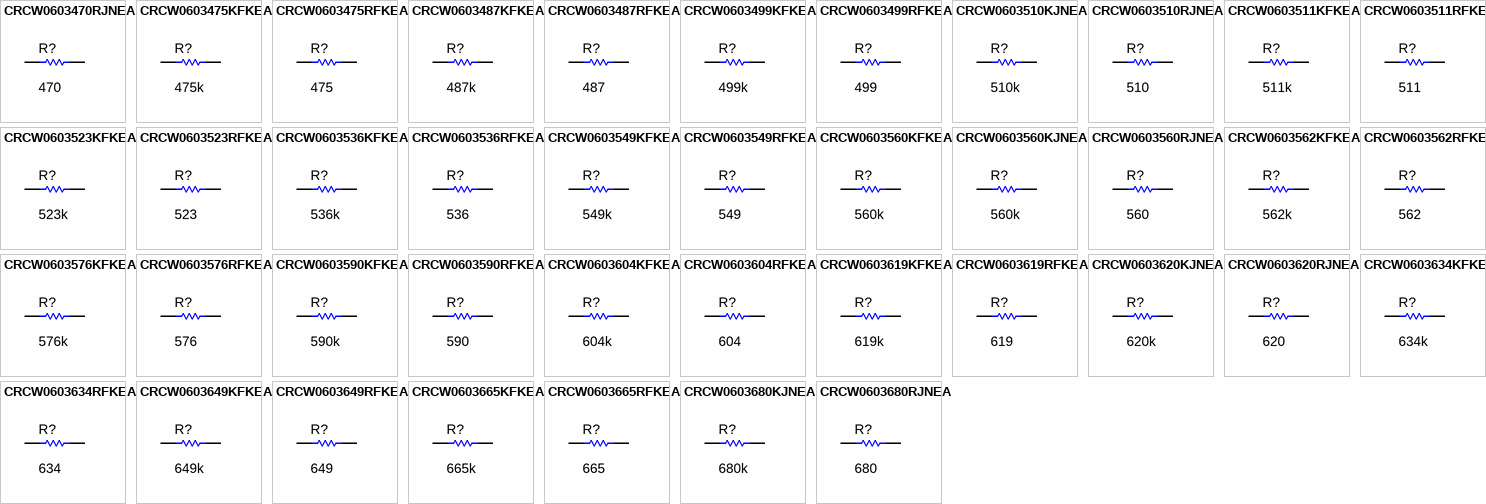
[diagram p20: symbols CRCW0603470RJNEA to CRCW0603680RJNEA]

## CRCW0603470RJNEA
designator R?  ValueDisplayed: 470  (hidden comment: CRCW0603470RJNEA)
RES, 470, 5%, 0.1 W, 0603; Manufacturer: Vishay-Dale; CompType: Resistor; Value: 470; Value_Code: 470R; Tolerance_%: 5; Power_W: 0.1; Value2: 0.1W; VDC_V: 75; TempCo: 200 ppm/C; SizeArea_mm2: 1.28; SizeX_mm: 1.6; SizeY_mm: 0.8; SizeZ_mm: 1; EIA_Code: E24; U/M: EA; AEC Category: Q200; Green_Lifecycle: Active; Green_REACh: Passed
signal-integrity model Resistor
simulation model Resistor
footprint 0603
footprint 0603M
footprint 0603L
footprint 0603_HV
footprint 0603S
pins: 1, 2

## CRCW0603475KFKEA
designator R?  ValueDisplayed: 475k  (hidden comment: CRCW0603475KFKEA)
RES, 475 k, 1%, 0.1 W, 0603; Manufacturer: Vishay-Dale; CompType: Resistor; Value: 475k; Res_ohm: 475000; Tolerance_%: 1; Power_W: 0.1; Value2: 0.1W; VDC_V: 75; TempCo: 100 ppm/C; SizeArea_mm2: 1.28; SizeX_mm: 1.6; SizeY_mm: 0.8; EIA_Code: E96; U/M: EA; AEC Category: Q200; Green_Lifecycle: Active; Green_REACh: Passed
signal-integrity model Resistor
simulation model Resistor
footprint 0603
footprint 0603M
footprint 0603L
footprint 0603_HV
footprint 0603S
pins: 1, 2

## CRCW0603475RFKEA
designator R?  ValueDisplayed: 475  (hidden comment: CRCW0603475RFKEA)
RES, 475, 1%, 0.1 W, 0603; Manufacturer: Vishay-Dale; CompType: Resistor; Value: 475; Value_Code: 475R; Tolerance_%: 1; Power_W: 0.1; Value2: 0.1W; VDC_V: 75; TempCo: 100 ppm/C; SizeArea_mm2: 1.28; SizeX_mm: 1.6; SizeY_mm: 0.8; EIA_Code: E96; U/M: EA; AEC Category: Q200; Green_Lifecycle: Active; Green_REACh: Passed
signal-integrity model Resistor
simulation model Resistor
footprint 0603
footprint 0603M
footprint 0603L
footprint 0603_HV
footprint 0603S
pins: 1, 2

## CRCW0603487KFKEA
designator R?  ValueDisplayed: 487k  (hidden comment: CRCW0603487KFKEA)
RES, 487 k, 1%, 0.1 W, 0603; Manufacturer: Vishay-Dale; CompType: Resistor; Value: 487k; Res_ohm: 487000; Tolerance_%: 1; Power_W: 0.1; Value2: 0.1W; VDC_V: 75; TempCo: 100 ppm/C; SizeArea_mm2: 1.28; SizeX_mm: 1.6; SizeY_mm: 0.8; EIA_Code: E96; U/M: EA; AEC Category: Q200; Green_Lifecycle: Active; Green_REACh: Passed
signal-integrity model Resistor
simulation model Resistor
footprint 0603
footprint 0603M
footprint 0603L
footprint 0603_HV
footprint 0603S
pins: 1, 2

## CRCW0603487RFKEA
designator R?  ValueDisplayed: 487  (hidden comment: CRCW0603487RFKEA)
RES, 487, 1%, 0.1 W, 0603; Manufacturer: Vishay-Dale; CompType: Resistor; Value: 487; Value_Code: 487R; Tolerance_%: 1; Power_W: 0.1; Value2: 0.1W; VDC_V: 75; TempCo: 100 ppm/C; SizeArea_mm2: 1.28; SizeX_mm: 1.6; SizeY_mm: 0.8; EIA_Code: E96; U/M: EA; AEC Category: Q200; Green_Lifecycle: Active; Green_REACh: Passed
signal-integrity model Resistor
simulation model Resistor
footprint 0603
footprint 0603M
footprint 0603L
footprint 0603_HV
footprint 0603S
pins: 1, 2

## CRCW0603499KFKEA
designator R?  ValueDisplayed: 499k  (hidden comment: CRCW0603499KFKEA)
RES, 499 k, 1%, 0.1 W, 0603; Manufacturer: Vishay-Dale; CompType: Resistor; Value: 499k; Res_ohm: 499000; Tolerance_%: 1; Power_W: 0.1; Value2: 0.1W; VDC_V: 75; TempCo: 100 ppm/C; SizeArea_mm2: 1.28; SizeX_mm: 1.6; SizeY_mm: 0.8; EIA_Code: E96; U/M: EA; AEC Category: Q200; Green_Lifecycle: Active; Green_REACh: Passed
signal-integrity model Resistor
simulation model Resistor
footprint 0603
footprint 0603M
footprint 0603L
footprint 0603_HV
footprint 0603S
pins: 1, 2

## CRCW0603499RFKEA
designator R?  ValueDisplayed: 499  (hidden comment: CRCW0603499RFKEA)
RES, 499, 1%, 0.1 W, 0603; Manufacturer: Vishay-Dale; CompType: Resistor; Value: 499; Value_Code: 499R; Tolerance_%: 1; Power_W: 0.1; Value2: 0.1W; VDC_V: 75; TempCo: 100 ppm/C; SizeArea_mm2: 1.28; SizeX_mm: 1.6; SizeY_mm: 0.8; EIA_Code: E96; U/M: EA; AEC Category: Q200; Green_Lifecycle: Active; Green_REACh: Passed
signal-integrity model Resistor
simulation model Resistor
footprint 0603
footprint 0603M
footprint 0603L
footprint 0603_HV
footprint 0603S
pins: 1, 2

## CRCW0603510KJNEA
designator R?  ValueDisplayed: 510k  (hidden comment: CRCW0603510KJNEA)
RES, 510 k, 5%, 0.1 W, 0603; Manufacturer: Vishay-Dale; CompType: Resistor; Value: 510k; Res_ohm: 510000; Tolerance_%: 5; Power_W: 0.1; Value2: 0.1W; VDC_V: 75; TempCo: 200 ppm/C; SizeArea_mm2: 1.28; SizeX_mm: 1.6; SizeY_mm: 0.8; SizeZ_mm: 1; EIA_Code: E24; U/M: EA; AEC Category: Q200; Green_Lifecycle: Active; Green_REACh: Passed
signal-integrity model Resistor
simulation model Resistor
footprint 0603
footprint 0603M
footprint 0603L
footprint 0603_HV
footprint 0603S
pins: 1, 2

## CRCW0603510RJNEA
designator R?  ValueDisplayed: 510  (hidden comment: CRCW0603510RJNEA)
RES, 510, 5%, 0.1 W, 0603; Manufacturer: Vishay-Dale; CompType: Resistor; Value: 510; Value_Code: 510R; Tolerance_%: 5; Power_W: 0.1; Value2: 0.1W; VDC_V: 75; TempCo: 200 ppm/C; SizeArea_mm2: 1.28; SizeX_mm: 1.6; SizeY_mm: 0.8; SizeZ_mm: 1; EIA_Code: E24; U/M: EA; AEC Category: Q200; Green_Lifecycle: Active; Green_REACh: Passed
signal-integrity model Resistor
simulation model Resistor
footprint 0603
footprint 0603M
footprint 0603L
footprint 0603_HV
footprint 0603S
pins: 1, 2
